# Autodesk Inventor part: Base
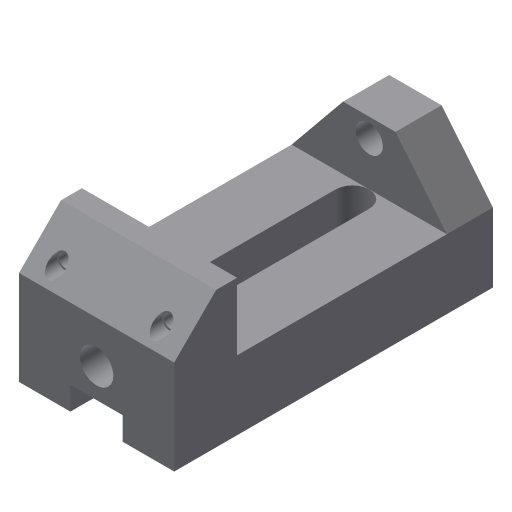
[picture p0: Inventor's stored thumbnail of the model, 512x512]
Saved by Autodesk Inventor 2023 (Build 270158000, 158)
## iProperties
Created: 2002-02
Part Number: Base
Document SubType Name: Modeling
Designer: ***
Density: 1 g/cm^3
Material: Generic
Appearance: Default
Control State: 0
Master: False
Checked Out: False
Shininess: 77.0
Length Units: 11269
Angle Units: 11279
Time Units: 11290
Mass Units: 11283
Length Display Precision: 3
Angle Display Precision: 2
Density: 0.0
Volumn: 0.0
Area: 0.0
PropertySet Name: Model Information
Author: ***
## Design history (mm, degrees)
sketch "Sketch2"
  geometry: L1 (-63.961, -4.254)-(-63.961, -37.254); L2 (-63.961, -37.254)-(88.039, -37.254); L3 (88.039, -37.254)-(88.039, 7.746); L4 (88.039, 7.746)-(68.039, 27.746); L5 (68.039, 27.746)-(58.039, 27.746); L6 (58.039, 27.746)-(58.039, -4.254); L7 (58.039, -4.254)-(-63.961, -4.254)
  constraints: 14 end point, 4 parallel, 1 perpendicular, 1 vertical
  dimensions: "d7" = 10 distance of L4.end L5.end; "d8" = 135 deg angle of L3 L4; "d9" = 33 distance of L1.start L1.end; "d10" = 152 distance of L1.end L2.end; "d11" = 65 distance between parallel lines of L5 L2; "d21" = 30 distance between parallel lines of L3 L6
extrude "Extrusion1" new body sketch "Sketch2" stored distance "d13" = 74; taper "d14" = 0 deg
sketch "Sketch3"
  geometry: L1 (0, 74)-(0, 0) reference; L2 (0, 0)-(-30, 24.5); L3 (-30, 24.5)-(-30, 49.5); L4 (-30, 49.5)-(0, 74); C1 r 6.5 at (-21, 37)
  constraints: 6 end point, 1 centre point, 1 equal length, 1 parallel
  dimensions: "d15" = 25 distance of L2.end L3.end; "d16" = 30 distance between parallel lines of L3 L1; "d17" = 13 diameter of C1; "d18" = 9 distance from line of L3 C1.centre
extrude "Extrusion2" join sketch "Sketch3" distance "d19" = 22; taper "d20" = 0 deg
sketch "Sketch4"
  geometry: L1 (0, 0)-(0, 74) reference; L2 (0, 0)-(45, 0) reference; C1 r 8 at (25, 37)
  constraints: 1 centre point
  dimensions: "d22" = 16 diameter of C1; "d23" = 25 distance from line of L1 C1.centre; "d24" = 37 distance from line of L2 C1.centre
extrude "Extrusion3" cut sketch "Sketch4" distance "d25" = 13; taper "d26" = 0 deg
sketch "Sketch5"
  geometry: L1 (45, 74)-(0, 74) reference; L2 (65, 0)-(65, 74) reference; 1 further point
  dimensions: "d27" = 12 distance from line of point (51, 62) L1; "d28" = 14 distance from line of L2 point (51, 62)
hole "Hole1" sketch "Sketch5" at (51, 62) diameter "d29" = 6; stored, may be unused: countersink angle "d33" = 82 deg, drill point angle "d35" = 0 deg; dims "d30" = 6, "d31" = 8, "d32" = 10, "d34" = 30
mirror "Mirror1"
sketch "Sketch6"
  geometry: L1 (100, 0)-(100, 74) reference; L2 (100, 74)-(0, 74) reference; L3 (14, 45)-(92, 45); L4 (92, 29)-(14, 29); A1 r 8 centre (92, 37) between (92, 29) and (92, 45); A2 r 8 centre (14, 37) between (14, 45) and (14, 29)
  constraints: 4 end point, 4 point on circle, 4 tangent, 2 centre point, 1 horizontal, 1 parallel
  dimensions: "d36" = 8 radius of A2; "d37" = 78 distance of L4.start L4.end; "d38" = 8 distance from line of L1 A1.centre; "d39" = 37 distance from line of L2 A2.centre
extrude "Extrusion4" cut sketch "Sketch6" extent not by distance; stored distance "d40" = 13; taper "d41" = 0 deg
sketch "Sketch7"
  geometry: L1 (0, 49.5)-(11, 49.5); L2 (11, 49.5)-(11, 24.5); L3 (11, 24.5)-(0, 24.5); L4 (0, 24.5)-(0, 49.5); L5 (45, 74)-(0, 74) reference; L6 (0, 0)-(0, 74) reference
  constraints: 8 end point, 2 parallel, 1 collinear, 1 horizontal, 1 perpendicular
  dimensions: "d42" = 25 distance of L3.end L1.start; "d43" = 11 distance of L1.start L1.end; "d44" = 24.5 distance between parallel lines of L5 L1
extrude "Extrusion5" cut sketch "Sketch7" extent not by distance; stored distance "d45" = 13; taper "d46" = 0 deg
body "Solid1"
